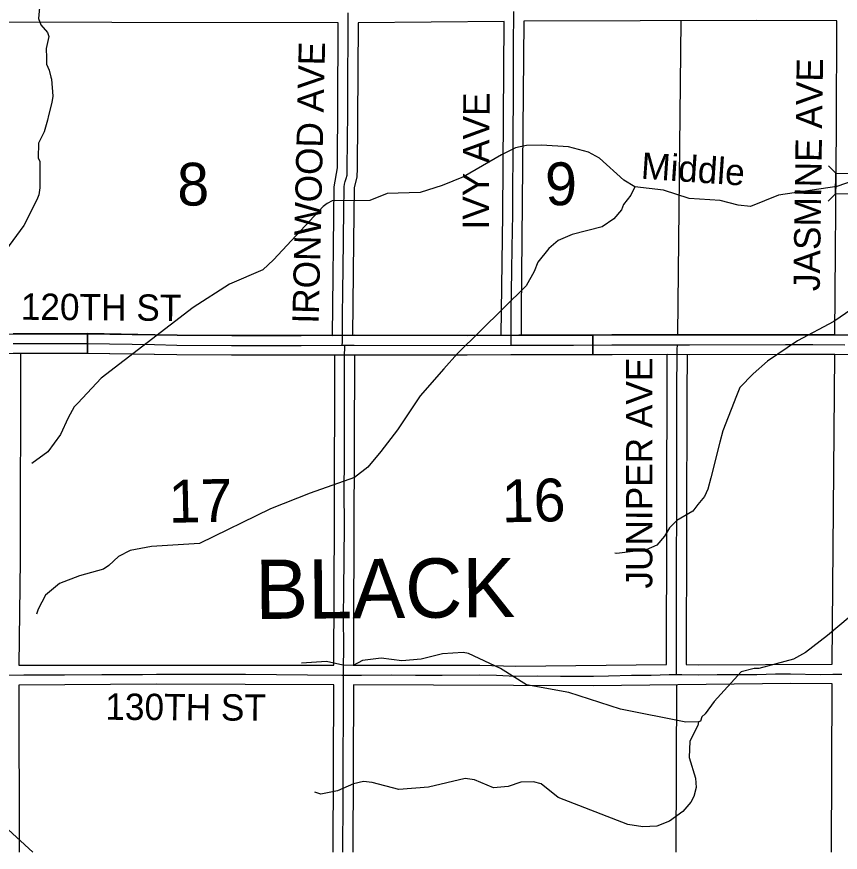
# Model space of a CAD drawing. Extents: x 10133 to 81668, y 7924 to 11018.
# Drawn here: x 11451.5 to 11826.5, y 8510.5 to 8891.2 of the extents above; entities that cross this region are included whole.
import ezdxf

# ---------------------------------------------------------------- set-up
doc = ezdxf.new("R2010")
doc.units = 0
for name, color, linetype in [('tdCoCityStreetMajor', 7, 'Continuous'), ('tdCoCityStreetMinor', 7, 'Continuous'), ('tdCoCorpTxt', 7, 'Continuous'), ('tdCoHydroRiver', 7, 'Continuous'), ('tdCoHydroTxtLg', 7, 'Continuous'), ('tdCoPriNonDiv', 7, 'Continuous'), ('tdCoRROwnerTxt', 7, 'Continuous'), ('tdCoSectLinePart', 7, 'Continuous'), ('tdCoShieldCoRte', 7, 'Continuous'), ('tdCoShieldStRte', 7, 'Continuous'), ('tdCoStrucNonDivPri', 7, 'Continuous'), ('tdCoSurfAsphalt', 7, 'Continuous')]:
    doc.layers.add(name, color=color, linetype=linetype)

msp = doc.modelspace()

# ---------------------------------------------------------------- linework, layer by layer
at = {"layer": 'tdCoCityStreetMajor'}
msp.add_lwpolyline([(11599.8, 8741.54), (11599.87, 8743), (11599.9, 8755.47), (11600.09, 8765.6), (11600.31, 8788.83), (11600.53, 8804.37), (11600.61, 8811.43), (11600.64, 8813.69), (11600.83, 8814.84), (11601.09, 8816.13), (11601.53, 8817.54), (11601.94, 8819.05), (11602.05, 8822.24), (11602.12, 8834.66), (11602.23, 8848.06), (11602.23, 8861.26), (11602.45, 8883.97), (11602.45, 8892.95)], dxfattribs=at)
at = {"layer": 'tdCoCityStreetMinor'}
for points in [[(11676.69, 8741.59), (11676.66, 8745.59), (11676.7, 8757.06), (11677.03, 8775.48), (11677.14, 8786.1), (11677.37, 8801.23), (11677.4, 8811.81), (11677.59, 8828.64), (11677.62, 8839.96), (11677.74, 8852.24), (11677.74, 8863.63), (11677.81, 8879.02), (11677.96, 8892.33), (11677.96, 8893.57)], [(11600.37, 8591.27), (11600.44, 8606.86), (11600.4, 8614.74), (11600.51, 8633.01), (11600.62, 8641.34), (11600.73, 8662.42), (11600.7, 8672.04), (11600.72, 8692.47), (11600.79, 8710.04), (11600.75, 8719.36), (11600.86, 8735.9), (11600.95, 8741.55)], [(11751.92, 8591.57), (11751.89, 8593.41), (11751.89, 8607.98), (11751.93, 8615.9), (11751.96, 8634.02), (11752, 8649.12), (11752.07, 8659.73), (11752.04, 8673.38), (11752.12, 8692.32), (11752.12, 8708.71), (11752.16, 8719.44), (11752.31, 8739.6), (11752.39, 8741.73)], [(11447.99, 8591.27), (11454.78, 8591.35), (11473.27, 8591.39), (11490.36, 8591.53), (11508.75, 8591.5), (11515.15, 8591.68), (11522.84, 8591.68), (11534.9, 8591.64), (11555.76, 8591.64), (11583.88, 8591.39), (11599.56, 8591.27), (11600.37, 8591.27)], [(11600.01, 8510.55), (11600.03, 8514.79), (11600.18, 8530.36), (11600.18, 8539.06), (11600.21, 8560.1), (11600.29, 8565.95), (11600.36, 8581.74), (11600.36, 8588.33), (11600.37, 8591.27)], [(11600.37, 8591.27), (11608.48, 8591.27), (11622.27, 8591.39), (11633.04, 8591.24), (11645.32, 8591.24), (11662.26, 8591.35), (11669.99, 8591.2), (11678.57, 8590.79), (11688.45, 8590.87), (11699.18, 8590.79), (11714.16, 8590.83), (11720.97, 8590.9), (11731.47, 8591.24), (11740.35, 8591.27), (11748.6, 8591.57), (11751.92, 8591.57)], [(11751.92, 8591.57), (11754.37, 8591.57), (11762.17, 8591.39), (11770.46, 8591.53), (11780.11, 8591.57), (11788.47, 8591.5), (11797.09, 8591.79), (11803.9, 8591.87), (11817.29, 8591.57), (11823.14, 8591.76), (11827.29, 8591.63)]]:
    msp.add_lwpolyline(points, dxfattribs=at)
at = {"layer": 'tdCoHydroRiver'}
for points in [[(11462.05, 8897.01), (11461.45, 8890.37), (11462.45, 8887.55), (11465.59, 8884.05), (11466.09, 8882.16), (11465, 8876.7), (11465.07, 8872.44), (11465.12, 8869.6), (11466.35, 8866.77), (11467.11, 8863.71), (11467.36, 8862.77), (11467.97, 8854.96), (11467.54, 8852.11), (11465.98, 8846.17), (11465.55, 8844.03), (11463.98, 8838.79), (11461.46, 8833.54), (11461.34, 8826.91), (11462.07, 8825.26), (11462.04, 8813.19), (11461.62, 8810.1), (11460.71, 8807.72), (11454.75, 8796.01), (11436.23, 8771.08)], [(11732.92, 8813.71), (11727.9, 8816.71), (11716.84, 8826.7), (11711.82, 8829.46), (11702.78, 8831.91), (11690.46, 8832.65), (11683.59, 8832.54), (11678.64, 8831.51), (11672.3, 8828.32), (11654.94, 8818.32), (11645.3, 8814.37), (11635.17, 8811.12), (11620.26, 8810.63), (11612.26, 8807.42), (11595.22, 8807.37), (11592.87, 8806.15)], [(11833.26, 8816.66), (11824.99, 8813.8), (11798.43, 8809.91), (11785.68, 8804.77)], [(11732.92, 8813.71), (11731.09, 8809.89), (11727.85, 8805.58), (11726.94, 8803.19), (11723.46, 8799.11), (11718.07, 8795.47), (11704.4, 8791.92), (11698.05, 8789.21), (11693.85, 8785.59), (11688.75, 8779.34), (11687.16, 8775.06), (11683.48, 8768.6), (11652.27, 8737.77), (11645.99, 8730.79), (11635.31, 8718.54), (11624.91, 8702.97), (11617.26, 8693.13), (11611.46, 8685.93), (11605.38, 8681.33), (11585.14, 8674.12), (11567.15, 8666.94), (11534.76, 8651.22), (11512.87, 8649.89), (11503.13, 8648.06), (11497.93, 8645.37), (11493.47, 8641.26)], [(11785.68, 8804.77), (11779.96, 8805.3), (11771.83, 8807.4), (11757.77, 8808.37), (11746.04, 8812.24), (11732.92, 8813.71)], [(11592.87, 8806.15), (11591, 8804.7), (11568.44, 8780.4), (11563.54, 8775.82), (11548.49, 8769.41), (11531.86, 8758.71), (11490.02, 8726.51), (11479.31, 8715.2), (11477.69, 8713.52), (11474.93, 8708.5), (11471.5, 8700.87), (11465.72, 8692.95), (11458.47, 8687.62)], [(11910.35, 8748.44), (11897.2, 8755.31), (11879.1, 8761.13), (11868.42, 8762.83), (11857.52, 8762.87), (11838.09, 8760.77), (11831.73, 8757.94), (11823.52, 8752.42), (11807.05, 8743.53), (11793.45, 8734.25), (11786.9, 8728.55)], [(11786.9, 8728.55), (11780.82, 8722.34), (11779.21, 8718.43), (11773.02, 8702.54), (11771.66, 8697.42), (11767.61, 8681.1), (11766.26, 8675.98), (11764.66, 8672.64), (11761.64, 8669.04), (11759.32, 8665.92), (11752.05, 8661.77), (11748.79, 8658.4), (11746.49, 8654.58), (11743.01, 8650.49), (11738.07, 8648.28), (11724.84, 8646.63), (11723.89, 8646.86)], [(11493.47, 8641.26), (11491.09, 8639.56), (11480.09, 8636.52), (11471.02, 8633.04), (11464.6, 8627.71), (11461.29, 8621.25), (11460.58, 8619.1)], [(11835.72, 8621.91), (11820.73, 8609.37), (11810.64, 8601.57), (11805.23, 8598.49), (11789.38, 8594.31)], [(11761.9, 8569.93), (11756.22, 8569.83), (11726.52, 8575.73), (11702.95, 8583.38), (11683.71, 8586.85), (11671.75, 8594.23), (11657.19, 8601.09), (11654.81, 8601.52), (11645.35, 8600.89), (11635.68, 8598.59), (11626.93, 8597.74), (11617.44, 8599), (11608.93, 8597.91), (11604.71, 8595.71), (11599.97, 8595.86), (11592.6, 8597.4), (11581.25, 8596.73)], [(11789.38, 8594.31), (11787.25, 8594.22), (11781.32, 8592.77), (11769.14, 8579.19), (11764.94, 8573.69), (11763.53, 8572.18), (11762.85, 8570.21), (11761.9, 8569.93)], [(11761.9, 8569.93), (11761.69, 8568.27), (11758.02, 8561.1), (11757.67, 8553.76), (11760.67, 8544.33), (11760.98, 8540.08), (11759.86, 8536.03), (11758.49, 8533.4), (11754.77, 8529.08), (11748.69, 8524.72), (11743.04, 8522.49), (11736.65, 8522.15), (11729.77, 8523.21), (11698.07, 8535.47), (11690.39, 8541.73), (11686.82, 8542.62), (11681.14, 8542.53), (11675.25, 8540.53), (11668.63, 8539.95), (11660.05, 8543.59), (11655.77, 8544.23), (11639.03, 8540.16), (11625.55, 8539.22), (11613.42, 8542.34), (11609.39, 8542.74), (11604.9, 8541.72), (11597.62, 8538.52), (11590.07, 8536.97), (11587.21, 8537.87)], [(11458.82, 8510.55), (11440.09, 8527.82), (11429.24, 8539.72)]]:
    msp.add_lwpolyline(points, dxfattribs=at)
at = {"layer": 'tdCoPriNonDiv'}
for points in [[(11595.38, 8746.02), (11596.14, 8813.76), (11597.55, 8822.33), (11597.96, 8884), (11597.96, 8888.46), (11391.68, 8888.71), (11294.72, 8888.45), (11297.06, 8746), (11483.67, 8746.8), (11524.54, 8746.1), (11595.38, 8746.02)], [(11672.17, 8746.06), (11672.87, 8801.27), (11673.42, 8889.03), (11606.95, 8888.46), (11606.54, 8822.08), (11606.36, 8818.22), (11605.13, 8813.29), (11604.81, 8788.78), (11604.37, 8746.06), (11672.17, 8746.06)], [(11824.04, 8746.25), (11824.85, 8841.31), (11825.01, 8889.3), (11788.41, 8889.45), (11682.42, 8889.11), (11681.2, 8757.01), (11681.16, 8746.1), (11824.04, 8746.25)], [(11596.23, 8662.42), (11596.38, 8737.03), (11524.45, 8737.1), (11483.64, 8737.81), (11453.21, 8737.77), (11453.14, 8643.68), (11452.54, 8595.82), (11595.89, 8595.8), (11596.23, 8662.42)], [(11747.39, 8596.03), (11747.58, 8659.74), (11747.75, 8737.25), (11605.38, 8737.07), (11604.9, 8614.74), (11604.89, 8595.77), (11662.35, 8595.85), (11678.66, 8595.29), (11747.39, 8596.03)], [(11762.19, 8595.88), (11822.82, 8596.25), (11824.02, 8737.25), (11814.02, 8737.36), (11756.79, 8737.22), (11756.66, 8719.41), (11756.39, 8596.02), (11762.19, 8595.88)], [(11595.66, 8510.55), (11595.86, 8586.8), (11515.21, 8587.18), (11452.44, 8586.71), (11452.66, 8510.55)], [(11822.5, 8510.55), (11822.76, 8587.24), (11803.88, 8587.37), (11714.17, 8586.33), (11604.86, 8586.78), (11604.58, 8510.55)]]:
    msp.add_lwpolyline(points, dxfattribs=at)
at = {"layer": 'tdCoSectLinePart'}
msp.add_lwpolyline([(11449.9, 8742.27), (11483.68, 8742.3), (11514.27, 8741.82), (11524.48, 8741.6), (11549.41, 8741.45), (11581.11, 8741.45), (11599.8, 8741.54), (11600.95, 8741.55), (11605.23, 8741.57), (11656.61, 8741.49), (11676.69, 8741.59), (11680.17, 8741.6), (11705.03, 8741.6), (11722.56, 8741.71), (11747.75, 8741.75), (11752.39, 8741.73), (11757.82, 8741.71), (11801.58, 8741.82), (11814.04, 8741.86), (11828.54, 8741.7)], dxfattribs=at)
at = {"layer": 'tdCoShieldCoRte'}
for points in [[(11820.95, 8807.21), (11824.32, 8810.48), (11824.46, 8819.86)], [(11821.2, 8823.23), (11824.46, 8819.86), (11833.85, 8819.71)], [(11836.97, 8806.96), (11833.7, 8810.33), (11824.32, 8810.48)]]:
    msp.add_lwpolyline(points, dxfattribs=at)
at = {"layer": 'tdCoStrucNonDivPri'}
msp.add_line((11751.91, 8587.03), (11751.64, 8510.55), dxfattribs=at)
msp.add_lwpolyline([(11753.92, 8889.34), (11752.43, 8746.24)], dxfattribs=at)
at = {"layer": 'tdCoSurfAsphalt'}
for points in [[(11132.89, 9033.19), (11132.88, 9035.44), (11141.88, 9035.44), (11146.71, 8738.97), (11294.17, 8746), (11308.79, 8746.04), (11334.35, 8746.15), (11366.91, 8746.3), (11391.58, 8746.26), (11425.21, 8746.56), (11449.9, 8746.78), (11483.73, 8746.82), (11483.73, 8737.82), (11483.67, 8737.82), (11449.95, 8737.78), (11425.29, 8737.56), (11391.61, 8737.26), (11366.93, 8737.3), (11334.39, 8737.15), (11308.82, 8737.04), (11294.37, 8737), (11219.06, 8732.98), (11137.76, 8729.58)], [(11483.73, 8746.82), (11514.38, 8746.34), (11524.56, 8746.11), (11549.45, 8745.97), (11581.12, 8745.97), (11605.24, 8746.08), (11656.63, 8746), (11680.19, 8746.11), (11705.04, 8746.11), (11713.8, 8746.17), (11713.8, 8737.17), (11705.07, 8737.11), (11680.21, 8737.11), (11656.64, 8737), (11605.26, 8737.08), (11581.14, 8736.97), (11549.42, 8736.97), (11524.44, 8737.11), (11514.21, 8737.34), (11483.73, 8737.82)], [(11879.13, 8736.94), (11852.75, 8737.19), (11833.62, 8737.16), (11814.05, 8737.37), (11801.61, 8737.34), (11757.84, 8737.23), (11747.77, 8737.26), (11722.6, 8737.23), (11713.8, 8737.17), (11713.8, 8746.17), (11722.57, 8746.23), (11747.78, 8746.26), (11757.84, 8746.23), (11801.59, 8746.34), (11814.08, 8746.37), (11833.66, 8746.16), (11852.78, 8746.19), (11879.14, 8745.94), (11879.14, 8736.94)]]:
    msp.add_lwpolyline(points, close=True, dxfattribs=at)
for points in [[(11833.64, 8746.15), (11814.06, 8746.36), (11801.56, 8746.32), (11757.82, 8746.21), (11747.76, 8746.25), (11722.55, 8746.21), (11705.02, 8746.1), (11680.16, 8746.1), (11656.6, 8745.99), (11605.22, 8746.07), (11581.1, 8745.95), (11549.42, 8745.95), (11524.54, 8746.1), (11514.35, 8746.32), (11483.71, 8746.8), (11449.88, 8746.77)], [(11833.66, 8746.16), (11814.08, 8746.37), (11801.59, 8746.34), (11757.84, 8746.23), (11747.78, 8746.26), (11722.57, 8746.23), (11705.04, 8746.11), (11680.19, 8746.11), (11656.63, 8746), (11605.24, 8746.08), (11581.12, 8745.97), (11549.45, 8745.97), (11524.56, 8746.11), (11514.38, 8746.34), (11483.73, 8746.82), (11449.9, 8746.78)], [(11833.59, 8737.15), (11814.02, 8737.36), (11801.59, 8737.32), (11757.81, 8737.21), (11747.75, 8737.25), (11722.58, 8737.21), (11705.04, 8737.1), (11680.18, 8737.1), (11656.62, 8736.99), (11605.24, 8737.07), (11581.12, 8736.95), (11549.4, 8736.95), (11524.41, 8737.1), (11514.18, 8737.32), (11483.64, 8737.8), (11449.93, 8737.77)], [(11833.62, 8737.16), (11814.05, 8737.37), (11801.61, 8737.34), (11757.84, 8737.23), (11747.77, 8737.26), (11722.6, 8737.23), (11705.07, 8737.11), (11680.21, 8737.11), (11656.64, 8737), (11605.26, 8737.08), (11581.14, 8736.97), (11549.42, 8736.97), (11524.44, 8737.11), (11514.21, 8737.34), (11483.67, 8737.82), (11449.95, 8737.78)]]:
    msp.add_lwpolyline(points, dxfattribs=at)

# ---------------------------------------------------------------- texts
at = {"layer": 'tdCoCorpTxt'}
msp.add_text('Middle', height=12, rotation=356.062, dxfattribs=at).set_placement((11735.52, 8817.45))
at = {"layer": 'tdCoHydroTxtLg'}
msp.add_text('BLACK', height=27, rotation=0.4281, dxfattribs=at).set_placement((11560.22, 8616.81))
at = {"layer": 'tdCoRROwnerTxt'}
for s, rotation, p in [('8', 1.1437, (11524.8, 8805.02)), ('9', 1.1445, (11692.33, 8805.19)), ('17', 1.1437, (11520.88, 8660.63)), ('16', 1.1444, (11672.58, 8660.83))]:
    msp.add_text(s, height=19.5, rotation=rotation, dxfattribs=at).set_placement(p)
at = {"layer": 'tdCoShieldStRte'}
for s, rotation, p in [('IRONWOOD AVE', 88.6744, (11589.02, 8751.26)), ('JASMINE AVE', 89.1739, (11817.17, 8766.12)), ('IVY AVE', 89.7064, (11666.54, 8794.21)), ('120TH ST', 359.5331, (11453.34, 8753.15)), ('JUNIPER AVE', 89.9704, (11740.96, 8630.68)), ('130TH ST', 359.6196, (11491.84, 8570.92))]:
    msp.add_text(s, height=12, rotation=rotation, dxfattribs=at).set_placement(p)

doc.saveas('drawing.dxf')
